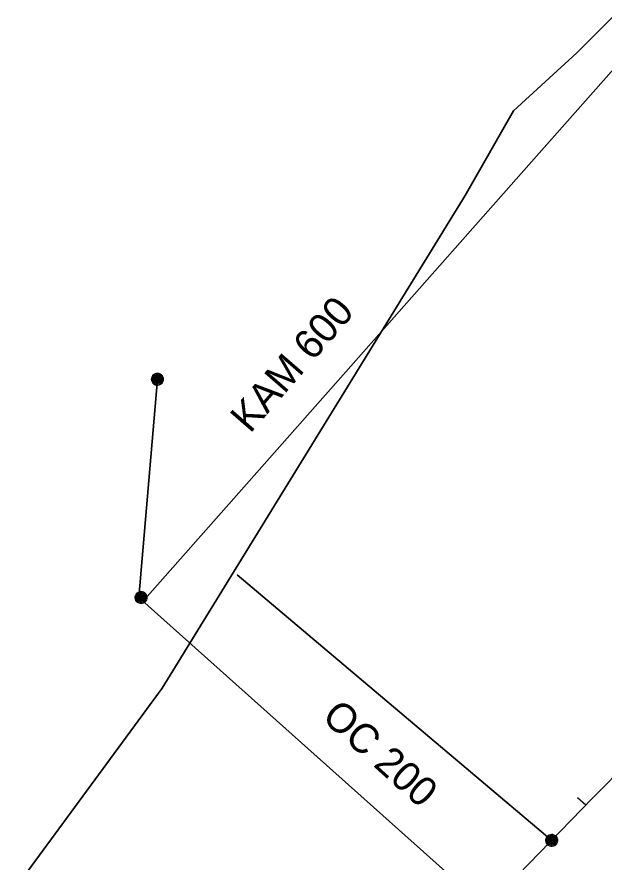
# Model space of a CAD drawing. Extents: x -867104 to -866746, y -1014489 to -1014255.
# Drawn here: x -866865.74 to -866843.66, y -1014431.21 to -1014399.43 of the extents above; entities that cross this region are included whole.
import ezdxf

# ---------------------------------------------------------------- set-up
doc = ezdxf.new("R2010")
doc.units = 0
doc.header["$LTSCALE"] = 0.44
doc.linetypes.add('DOT_DASHED', pattern=[7.7, 5, -1.2, 0.3, -1.2])
for name, color, linetype, lineweight in [('1', 7, 'Continuous', 35), ('12', 7, 'Continuous', 13), ('21', 7, 'Continuous', 35), ('30', 7, 'Continuous', 13), ('34', 7, 'Continuous', 13)]:
    doc.layers.add(name, color=color, linetype=linetype, lineweight=lineweight)

msp = doc.modelspace()

# ---------------------------------------------------------------- linework, layer by layer
at = {"layer": '1'}
msp.add_line((-866845.63, -1014430.388), (-866857.458, -1014420.408), dxfattribs=at)
at = {"layer": '1', "linetype": 'DOT_DASHED', "lineweight": 25}
msp.add_line((-866844.343, -1014429.061), (-866844.657, -1014428.789), dxfattribs=at)
at = {"layer": '1'}
for points in [[(-866840.01, -1014396.11), (-866844.69, -1014400.78), (-866847.06, -1014402.96), (-866848.88, -1014406.15), (-866860.28, -1014424.67), (-866871.77, -1014440.29), (-866875.11, -1014444.27), (-866876.93, -1014446.09), (-866879, -1014449.37), (-866879.17, -1014450.73), (-866879.17, -1014451.68), (-866879.03, -1014452.53), (-866876.52, -1014455.41), (-866874.72, -1014458.69), (-866874.8, -1014459.33), (-866875.66, -1014460.47), (-866876.85, -1014461.77), (-866877.992, -1014463.135), (-866881.12, -1014466.73), (-866885.53, -1014471.37), (-866892.467, -1014476.423)], [(-866829.29, -1014413.39), (-866837.14, -1014421.79), (-866844.09, -1014428.8), (-866855.26, -1014440.32), (-866867.329, -1014452.641), (-866873.974, -1014459.295), (-866875.079, -1014460.444), (-866876.617, -1014462.044), (-866877.133, -1014462.581), (-866877.679, -1014463.149)]]:
    msp.add_lwpolyline(points, dxfattribs=at)
at = {"layer": '12'}
for points in [[(-866845.399, -1014430.388), (-866845.405, -1014430.336), (-866845.422, -1014430.286), (-866845.451, -1014430.242), (-866845.488, -1014430.205), (-866845.533, -1014430.178), (-866845.583, -1014430.161), (-866845.636, -1014430.157), (-866845.688, -1014430.164), (-866845.737, -1014430.183), (-866845.78, -1014430.212), (-866845.816, -1014430.251), (-866845.842, -1014430.296), (-866845.858, -1014430.347), (-866845.861, -1014430.399), (-866845.853, -1014430.451), (-866845.833, -1014430.5), (-866845.802, -1014430.543), (-866845.763, -1014430.577), (-866845.717, -1014430.603), (-866845.666, -1014430.617), (-866845.613, -1014430.619), (-866845.562, -1014430.609), (-866845.514, -1014430.588), (-866845.471, -1014430.557), (-866845.437, -1014430.516), (-866845.413, -1014430.47), (-866845.401, -1014430.419)], [(-866845.429, -1014430.388), (-866845.435, -1014430.339), (-866845.452, -1014430.293), (-866845.48, -1014430.253), (-866845.517, -1014430.221), (-866845.561, -1014430.199), (-866845.609, -1014430.188), (-866845.658, -1014430.188), (-866845.705, -1014430.201), (-866845.748, -1014430.225), (-866845.784, -1014430.258), (-866845.811, -1014430.299), (-866845.827, -1014430.346), (-866845.831, -1014430.395), (-866845.824, -1014430.443), (-866845.805, -1014430.488), (-866845.775, -1014430.528), (-866845.737, -1014430.559), (-866845.693, -1014430.579), (-866845.645, -1014430.589), (-866845.596, -1014430.587), (-866845.549, -1014430.572), (-866845.506, -1014430.547), (-866845.472, -1014430.513), (-866845.446, -1014430.471), (-866845.432, -1014430.424)], [(-866845.459, -1014430.388), (-866845.465, -1014430.343), (-866845.482, -1014430.301), (-866845.51, -1014430.266), (-866845.546, -1014430.239), (-866845.588, -1014430.222), (-866845.633, -1014430.217), (-866845.678, -1014430.223), (-866845.719, -1014430.242), (-866845.754, -1014430.27), (-866845.781, -1014430.307), (-866845.797, -1014430.349), (-866845.801, -1014430.394), (-866845.794, -1014430.439), (-866845.775, -1014430.48), (-866845.746, -1014430.514), (-866845.709, -1014430.54), (-866845.666, -1014430.556), (-866845.621, -1014430.559), (-866845.576, -1014430.551), (-866845.536, -1014430.531), (-866845.502, -1014430.502), (-866845.476, -1014430.464), (-866845.462, -1014430.421)], [(-866845.489, -1014430.388), (-866845.494, -1014430.347), (-866845.512, -1014430.31), (-866845.539, -1014430.279), (-866845.574, -1014430.258), (-866845.614, -1014430.247), (-866845.655, -1014430.249), (-866845.694, -1014430.262), (-866845.728, -1014430.286), (-866845.753, -1014430.318), (-866845.768, -1014430.356), (-866845.771, -1014430.397), (-866845.763, -1014430.437), (-866845.743, -1014430.473), (-866845.714, -1014430.502), (-866845.677, -1014430.521), (-866845.637, -1014430.529), (-866845.596, -1014430.525), (-866845.558, -1014430.51), (-866845.526, -1014430.484), (-866845.503, -1014430.45), (-866845.49, -1014430.411)], [(-866845.519, -1014430.388), (-866845.524, -1014430.352), (-866845.542, -1014430.32), (-866845.568, -1014430.295), (-866845.602, -1014430.28), (-866845.638, -1014430.277), (-866845.673, -1014430.285), (-866845.704, -1014430.305), (-866845.727, -1014430.333), (-866845.74, -1014430.367), (-866845.74, -1014430.404), (-866845.729, -1014430.439), (-866845.708, -1014430.468), (-866845.678, -1014430.489), (-866845.643, -1014430.499), (-866845.606, -1014430.497), (-866845.572, -1014430.483), (-866845.545, -1014430.46), (-866845.526, -1014430.428), (-866845.519, -1014430.393)], [(-866845.549, -1014430.388), (-866845.554, -1014430.357), (-866845.571, -1014430.331), (-866845.597, -1014430.314), (-866845.627, -1014430.307), (-866845.658, -1014430.311), (-866845.685, -1014430.328), (-866845.703, -1014430.352), (-866845.711, -1014430.383), (-866845.707, -1014430.413), (-866845.692, -1014430.441), (-866845.668, -1014430.46), (-866845.638, -1014430.469), (-866845.607, -1014430.466), (-866845.579, -1014430.452), (-866845.559, -1014430.428), (-866845.549, -1014430.399)], [(-866845.579, -1014430.388), (-866845.584, -1014430.364), (-866845.601, -1014430.346), (-866845.624, -1014430.337), (-866845.648, -1014430.34), (-866845.669, -1014430.354), (-866845.68, -1014430.376), (-866845.68, -1014430.401), (-866845.668, -1014430.422), (-866845.648, -1014430.436), (-866845.623, -1014430.439), (-866845.6, -1014430.43), (-866845.584, -1014430.412)], [(-866845.609, -1014430.388), (-866845.614, -1014430.373), (-866845.629, -1014430.367), (-866845.644, -1014430.371), (-866845.651, -1014430.385), (-866845.647, -1014430.4), (-866845.634, -1014430.409), (-866845.619, -1014430.406), (-866845.609, -1014430.394)]]:
    msp.add_lwpolyline(points, close=True, dxfattribs=at)
at = {"layer": '21'}
for p, q in [((-866860.923, -1014421.324), (-866846.197, -1014404.673)), ((-866861.15, -1014421.261), (-866860.453, -1014413.056))]:
    msp.add_line(p, q, dxfattribs=at)
for points in [[(-866846.197, -1014404.673), (-866828.183, -1014384.303), (-866770.762, -1014326.42)], [(-866851.61, -1014443.23), (-866844.093, -1014436.497), (-866861.15, -1014421.261)]]:
    msp.add_lwpolyline(points, dxfattribs=at)
at = {"layer": '30'}
for points in [[(-866860.838, -1014421.261), (-866860.844, -1014421.209), (-866860.861, -1014421.159), (-866860.89, -1014421.115), (-866860.927, -1014421.078), (-866860.972, -1014421.051), (-866861.022, -1014421.034), (-866861.075, -1014421.03), (-866861.127, -1014421.037), (-866861.176, -1014421.056), (-866861.219, -1014421.085), (-866861.255, -1014421.124), (-866861.281, -1014421.169), (-866861.297, -1014421.22), (-866861.3, -1014421.272), (-866861.292, -1014421.324), (-866861.272, -1014421.373), (-866861.241, -1014421.416), (-866861.202, -1014421.45), (-866861.156, -1014421.476), (-866861.105, -1014421.49), (-866861.052, -1014421.492), (-866861.001, -1014421.482), (-866860.953, -1014421.461), (-866860.91, -1014421.43), (-866860.876, -1014421.389), (-866860.852, -1014421.343), (-866860.84, -1014421.292)], [(-866860.868, -1014421.261), (-866860.874, -1014421.212), (-866860.891, -1014421.166), (-866860.919, -1014421.126), (-866860.956, -1014421.094), (-866861, -1014421.072), (-866861.048, -1014421.061), (-866861.097, -1014421.061), (-866861.144, -1014421.074), (-866861.187, -1014421.098), (-866861.223, -1014421.131), (-866861.25, -1014421.172), (-866861.266, -1014421.219), (-866861.27, -1014421.268), (-866861.263, -1014421.316), (-866861.244, -1014421.361), (-866861.214, -1014421.401), (-866861.176, -1014421.432), (-866861.132, -1014421.452), (-866861.084, -1014421.462), (-866861.035, -1014421.46), (-866860.988, -1014421.445), (-866860.945, -1014421.42), (-866860.911, -1014421.386), (-866860.885, -1014421.344), (-866860.871, -1014421.297)], [(-866860.898, -1014421.261), (-866860.904, -1014421.216), (-866860.921, -1014421.174), (-866860.949, -1014421.139), (-866860.985, -1014421.112), (-866861.027, -1014421.095), (-866861.072, -1014421.09), (-866861.117, -1014421.096), (-866861.158, -1014421.115), (-866861.193, -1014421.143), (-866861.22, -1014421.18), (-866861.236, -1014421.222), (-866861.24, -1014421.267), (-866861.233, -1014421.312), (-866861.214, -1014421.353), (-866861.185, -1014421.387), (-866861.148, -1014421.413), (-866861.105, -1014421.429), (-866861.06, -1014421.432), (-866861.015, -1014421.424), (-866860.975, -1014421.404), (-866860.941, -1014421.375), (-866860.915, -1014421.337), (-866860.901, -1014421.294)], [(-866860.928, -1014421.261), (-866860.933, -1014421.22), (-866860.951, -1014421.183), (-866860.978, -1014421.152), (-866861.013, -1014421.131), (-866861.053, -1014421.12), (-866861.094, -1014421.122), (-866861.133, -1014421.135), (-866861.167, -1014421.159), (-866861.192, -1014421.191), (-866861.207, -1014421.229), (-866861.21, -1014421.27), (-866861.202, -1014421.31), (-866861.182, -1014421.346), (-866861.153, -1014421.375), (-866861.116, -1014421.394), (-866861.076, -1014421.402), (-866861.035, -1014421.398), (-866860.997, -1014421.383), (-866860.965, -1014421.357), (-866860.942, -1014421.323), (-866860.929, -1014421.284)], [(-866860.958, -1014421.261), (-866860.963, -1014421.225), (-866860.981, -1014421.193), (-866861.007, -1014421.168), (-866861.041, -1014421.153), (-866861.077, -1014421.15), (-866861.112, -1014421.158), (-866861.143, -1014421.178), (-866861.166, -1014421.206), (-866861.179, -1014421.24), (-866861.179, -1014421.277), (-866861.168, -1014421.312), (-866861.147, -1014421.341), (-866861.117, -1014421.362), (-866861.082, -1014421.372), (-866861.045, -1014421.37), (-866861.011, -1014421.356), (-866860.984, -1014421.333), (-866860.965, -1014421.301), (-866860.958, -1014421.266)], [(-866860.988, -1014421.261), (-866860.993, -1014421.23), (-866861.01, -1014421.204), (-866861.036, -1014421.187), (-866861.066, -1014421.18), (-866861.097, -1014421.184), (-866861.124, -1014421.201), (-866861.142, -1014421.225), (-866861.15, -1014421.256), (-866861.146, -1014421.286), (-866861.131, -1014421.314), (-866861.107, -1014421.333), (-866861.077, -1014421.342), (-866861.046, -1014421.339), (-866861.018, -1014421.325), (-866860.998, -1014421.301), (-866860.988, -1014421.272)], [(-866861.018, -1014421.261), (-866861.023, -1014421.237), (-866861.04, -1014421.219), (-866861.063, -1014421.21), (-866861.087, -1014421.213), (-866861.108, -1014421.227), (-866861.119, -1014421.249), (-866861.119, -1014421.274), (-866861.107, -1014421.295), (-866861.087, -1014421.309), (-866861.062, -1014421.312), (-866861.039, -1014421.303), (-866861.023, -1014421.285)], [(-866861.048, -1014421.261), (-866861.053, -1014421.246), (-866861.068, -1014421.24), (-866861.083, -1014421.244), (-866861.09, -1014421.258), (-866861.086, -1014421.273), (-866861.073, -1014421.282), (-866861.058, -1014421.279), (-866861.048, -1014421.267)]]:
    msp.add_lwpolyline(points, close=True, dxfattribs=at)
at = {"layer": '34'}
for points in [[(-866860.222, -1014413.056), (-866860.228, -1014413.004), (-866860.245, -1014412.954), (-866860.274, -1014412.91), (-866860.311, -1014412.873), (-866860.356, -1014412.846), (-866860.406, -1014412.829), (-866860.459, -1014412.825), (-866860.511, -1014412.832), (-866860.559, -1014412.851), (-866860.603, -1014412.88), (-866860.639, -1014412.919), (-866860.665, -1014412.964), (-866860.681, -1014413.015), (-866860.684, -1014413.067), (-866860.676, -1014413.119), (-866860.656, -1014413.168), (-866860.625, -1014413.211), (-866860.586, -1014413.245), (-866860.54, -1014413.271), (-866860.489, -1014413.285), (-866860.436, -1014413.287), (-866860.385, -1014413.277), (-866860.337, -1014413.256), (-866860.294, -1014413.225), (-866860.26, -1014413.184), (-866860.236, -1014413.138), (-866860.223, -1014413.087)], [(-866860.252, -1014413.056), (-866860.258, -1014413.007), (-866860.275, -1014412.961), (-866860.303, -1014412.921), (-866860.34, -1014412.889), (-866860.384, -1014412.867), (-866860.432, -1014412.856), (-866860.481, -1014412.856), (-866860.527, -1014412.869), (-866860.571, -1014412.893), (-866860.607, -1014412.926), (-866860.634, -1014412.967), (-866860.65, -1014413.014), (-866860.654, -1014413.063), (-866860.647, -1014413.111), (-866860.628, -1014413.156), (-866860.598, -1014413.196), (-866860.559, -1014413.227), (-866860.516, -1014413.247), (-866860.468, -1014413.257), (-866860.419, -1014413.255), (-866860.372, -1014413.24), (-866860.329, -1014413.215), (-866860.294, -1014413.181), (-866860.269, -1014413.139), (-866860.255, -1014413.092)], [(-866860.282, -1014413.056), (-866860.288, -1014413.011), (-866860.304, -1014412.969), (-866860.333, -1014412.934), (-866860.369, -1014412.907), (-866860.411, -1014412.89), (-866860.456, -1014412.885), (-866860.5, -1014412.891), (-866860.542, -1014412.91), (-866860.576, -1014412.938), (-866860.603, -1014412.975), (-866860.62, -1014413.017), (-866860.624, -1014413.062), (-866860.617, -1014413.107), (-866860.598, -1014413.148), (-866860.569, -1014413.182), (-866860.532, -1014413.208), (-866860.489, -1014413.224), (-866860.444, -1014413.227), (-866860.399, -1014413.219), (-866860.358, -1014413.199), (-866860.325, -1014413.17), (-866860.299, -1014413.132), (-866860.285, -1014413.089)], [(-866860.312, -1014413.056), (-866860.316, -1014413.015), (-866860.335, -1014412.978), (-866860.362, -1014412.947), (-866860.397, -1014412.926), (-866860.437, -1014412.915), (-866860.478, -1014412.917), (-866860.517, -1014412.93), (-866860.551, -1014412.954), (-866860.576, -1014412.986), (-866860.591, -1014413.024), (-866860.593, -1014413.065), (-866860.586, -1014413.105), (-866860.566, -1014413.141), (-866860.537, -1014413.17), (-866860.5, -1014413.189), (-866860.46, -1014413.197), (-866860.419, -1014413.193), (-866860.38, -1014413.178), (-866860.348, -1014413.152), (-866860.326, -1014413.118), (-866860.313, -1014413.079)], [(-866860.342, -1014413.056), (-866860.347, -1014413.02), (-866860.365, -1014412.988), (-866860.391, -1014412.963), (-866860.424, -1014412.948), (-866860.461, -1014412.945), (-866860.495, -1014412.953), (-866860.527, -1014412.973), (-866860.549, -1014413.001), (-866860.563, -1014413.035), (-866860.563, -1014413.072), (-866860.552, -1014413.107), (-866860.531, -1014413.136), (-866860.5, -1014413.157), (-866860.466, -1014413.167), (-866860.429, -1014413.165), (-866860.395, -1014413.151), (-866860.368, -1014413.128), (-866860.348, -1014413.096), (-866860.342, -1014413.061)], [(-866860.372, -1014413.056), (-866860.377, -1014413.025), (-866860.394, -1014412.999), (-866860.419, -1014412.982), (-866860.45, -1014412.975), (-866860.481, -1014412.979), (-866860.508, -1014412.996), (-866860.526, -1014413.02), (-866860.534, -1014413.051), (-866860.53, -1014413.081), (-866860.515, -1014413.109), (-866860.49, -1014413.128), (-866860.461, -1014413.137), (-866860.429, -1014413.134), (-866860.402, -1014413.12), (-866860.382, -1014413.096), (-866860.372, -1014413.067)], [(-866860.402, -1014413.056), (-866860.407, -1014413.032), (-866860.424, -1014413.014), (-866860.446, -1014413.005), (-866860.471, -1014413.008), (-866860.492, -1014413.022), (-866860.503, -1014413.044), (-866860.503, -1014413.069), (-866860.49, -1014413.09), (-866860.471, -1014413.104), (-866860.446, -1014413.107), (-866860.423, -1014413.098), (-866860.407, -1014413.08)], [(-866860.432, -1014413.056), (-866860.437, -1014413.041), (-866860.451, -1014413.035), (-866860.467, -1014413.039), (-866860.473, -1014413.053), (-866860.47, -1014413.068), (-866860.456, -1014413.077), (-866860.441, -1014413.074), (-866860.432, -1014413.062)]]:
    msp.add_lwpolyline(points, close=True, dxfattribs=at)

# ---------------------------------------------------------------- texts
at = {"layer": '1'}
for s, rotation, p in [('KAM 600 ', 49, (-866856.971, -1014415.12)), ('OC 200', 318, (-866854.316, -1014425.822))]:
    msp.add_text(s, height=1.1, rotation=rotation, dxfattribs=at).set_placement(p)

doc.saveas('drawing.dxf')
